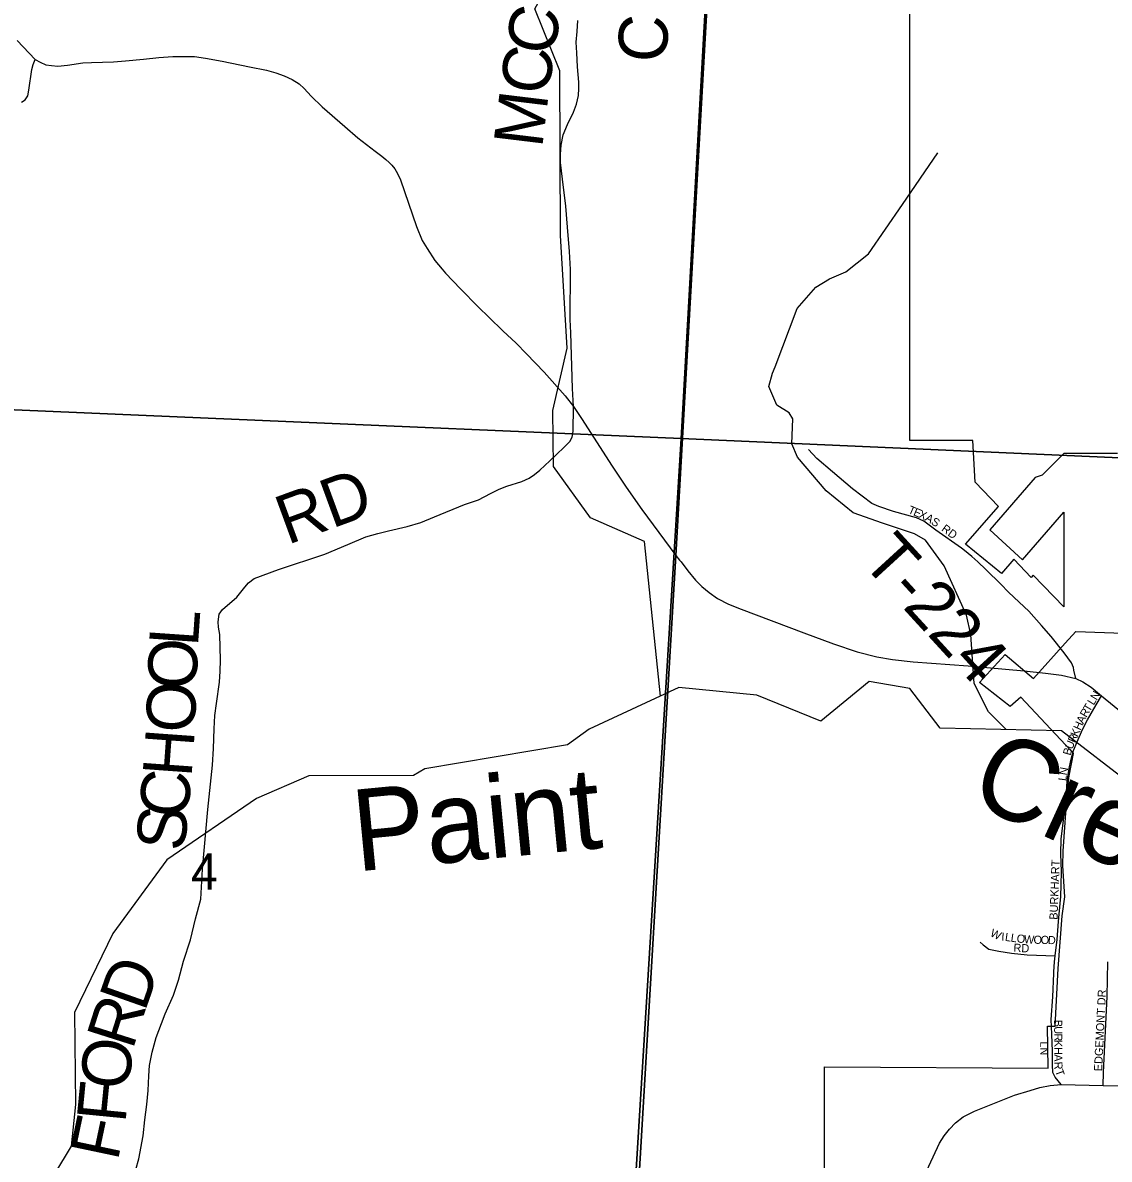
# Model space of a CAD drawing. Extents: x 1878108 to 2183446, y 146837 to 508383.
# Drawn here: x 2042273 to 2048929, y 293449 to 300413 of the extents above; entities that cross this region are included whole.
import ezdxf

# ---------------------------------------------------------------- set-up
doc = ezdxf.new("R2010")
doc.units = 0
for name, color, linetype in [('GM_X_City_Street', 7, 'Continuous'), ('GM_X_City_Street_Text', 7, 'Continuous'), ('GM_X_Corporation', 7, 'Continuous'), ('GM_X_County_Road', 7, 'Continuous'), ('GM_X_County_Road_Text', 7, 'Continuous'), ('GM_X_Minor_River', 7, 'Continuous'), ('GM_X_Minor_River_Text', 7, 'Continuous'), ('GM_X_Section', 7, 'Continuous'), ('GM_X_Section_Text', 7, 'Continuous'), ('GM_X_State_Route', 7, 'Continuous'), ('GM_X_Township', 7, 'Continuous'), ('GM_X_Township_Road', 7, 'Continuous'), ('GM_X_Township_Road_Text', 7, 'Continuous'), ('GM_X_Township_Subdivision', 7, 'Continuous'), ('GM_X_Township_Subdivision_Text', 7, 'Continuous')]:
    doc.layers.add(name, color=color, linetype=linetype)

msp = doc.modelspace()

# ---------------------------------------------------------------- linework, layer by layer
at = {"layer": 'GM_X_City_Street'}
for points in [[(2048723.1, 296394.8), (2048712.2, 296446.1)], [(2048696.9, 295908.5), (2048709.8, 295953.8), (2048732, 296006.9), (2048765.2, 296081.2), (2048794.3, 296141.8), (2048848.3, 296234.1), (2048882, 296288.6)], [(2048891.1, 293900), (2048893.7, 293980), (2048914.9, 294445.8), (2048914.8, 294445.9), (2048920.8, 294657.6)], [(2048633.8, 293906.7), (2048596.7, 293951.4), (2048583.9, 293980), (2048580.1, 294026.5), (2048580.1, 294111.6), (2048577.6, 294212.6)]]:
    msp.add_lwpolyline(points, dxfattribs=at)
at = {"layer": 'GM_X_Corporation'}
for points in [[(2048978.2, 297773.1), (2048650.2, 297773.1), (2048517.9, 297640.9), (2048475.7, 297625.5), (2048197.5, 297305.5), (2048396.9, 297122), (2048650.1, 297413.2), (2048650.1, 296834.3), (2048462.6, 297028.5), (2048450.1, 297014.2), (2048343.1, 297124.9), (2048267.7, 297038.2), (2048048.2, 297216.9), (2048250.3, 297449.3), (2048107.2, 297597.5), (2048093.8, 297853.1), (2047707.8, 297853.1), (2047707.7, 300742.9)], [(2047182.7, 292397.4), (2047183.4, 294014.9), (2048554.9, 294007.4), (2048550.8, 294264.7), (2048571.8, 294264.2), (2048596.2, 294263.4), (2048615.2, 294618.2), (2048639.2, 294940.7), (2048655.9, 295056.6), (2048643.8, 295246.6), (2048645.9, 295335.9), (2048673.7, 295716.7), (2048683.2, 295797.2), (2048709.9, 295935), (2048690.5, 295955.4), (2048386.1, 296281), (2048321.8, 296222.8), (2048133, 296369.3), (2048291.7, 296541.8), (2048464.4, 296395.3), (2048657.6, 296611.1), (2048723.5, 296682.3), (2049892.6, 296642.2)]]:
    msp.add_lwpolyline(points, dxfattribs=at)
at = {"layer": 'GM_X_County_Road'}
msp.add_lwpolyline([(2045647.3, 298061.2), (2045640.7, 298170.9), (2045629.6, 298513.3), (2045625.3, 298594.2), (2045629, 298900.7), (2045621.5, 299010), (2045610.2, 299159.5), (2045598.9, 299288.9), (2045578.8, 299453.4), (2045567.5, 299556.4), (2045566.2, 299605.4), (2045571.2, 299661.9), (2045582.5, 299726), (2045608.9, 299788.8), (2045646.6, 299864.2), (2045665.4, 299914.4), (2045678, 299967.2), (2045679.3, 300009.9), (2045679.3, 300047.6), (2045671.7, 300143), (2045666.7, 300228.4), (2045662.9, 300293.8), (2045668.5, 300359.5), (2045673, 300425.7)], dxfattribs=at)
at = {"layer": 'GM_X_Minor_River'}
for points in [[(2046178.6, 296286.3), (2046081, 297234.6), (2045750.4, 297379.9), (2045523.8, 297694.5), (2045519.3, 298037.1), (2045608.4, 298418.6), (2045567.3, 299109.5), (2045562, 300117.5), (2045408.7, 300498.8), (2045575.1, 300796.9), (2045599.4, 301083.7)], [(2048296.3, 296081.2), (2048189.8, 296189.9), (2048101.8, 296364.4), (2048079.9, 296663.5), (2048053.9, 296781.9), (2047917.9, 297084.8), (2047801.9, 297241.2), (2047735.8, 297281.3), (2047539.7, 297345.3), (2047359.6, 297409.4), (2047193.5, 297543.7), (2047019.5, 297750.2), (2046983.5, 297832.5), (2046989.5, 297985), (2046967.5, 298023.1), (2046891.5, 298069.2), (2046843.5, 298183.6), (2046865.5, 298265.9), (2046881.6, 298304.1), (2047015.8, 298661.5), (2047131.9, 298792.1), (2047214, 298844.4), (2047314.1, 298886.6), (2047454.2, 298997.2), (2047662.5, 299298.5), (2047878.8, 299615.9)], [(2049071.3, 295738.5), (2048635.9, 296073.3), (2047892.1, 296090.6), (2047706.5, 296333.5), (2047457.4, 296375.3), (2047161.9, 296132.2), (2046768.9, 296293), (2046291.3, 296338.8), (2045743.4, 296083.5), (2045610.4, 295988.1), (2044736.4, 295840), (2044666.8, 295799.3), (2044025.4, 295797.6), (2043704.5, 295658.5), (2043156.3, 295282.9), (2042825.5, 294831.1), (2042589.3, 294348.1), (2042596.7, 293785.2), (2042570, 293528.5), (2042275.8, 293040.9), (2042389.6, 292771.4), (2043259.2, 292031.8)]]:
    msp.add_lwpolyline(points, dxfattribs=at)
at = {"layer": 'GM_X_Section'}
for points in [[(2046608.5, 303278.4), (2046305.3, 297866), (2040795.1, 298102.8), (2041118.3, 303517.3)], [(2046608.5, 303278.4), (2052098.8, 303033.5), (2051725.6, 297626.8), (2046305.3, 297866)], [(2046305.3, 297866), (2045974, 292455.4), (2040477.8, 292684.4), (2040533.2, 293648.8), (2040666, 295882.7), (2040795.1, 298102.8)], [(2046305.3, 297866), (2051725.6, 297626.8), (2051406.4, 292766.4), (2051368.5, 292736.3), (2051314.6, 292690.1), (2051262.8, 292641.9), (2051200.9, 292591.7), (2051101.2, 292499.3), (2050981.6, 292386.8), (2050889.9, 292300.5), (2050854, 292266.4), (2050820.1, 292230.3), (2045974, 292455.4)]]:
    msp.add_lwpolyline(points, close=True, dxfattribs=at)
at = {"layer": 'GM_X_State_Route'}
for points in [[(2042238.6, 300303.5), (2042348, 300186.7), (2042379, 300171.9), (2042414.7, 300155.2), (2042449.2, 300149.7), (2042487.1, 300147.4), (2042547.3, 300153), (2042639.8, 300166.4), (2042694.4, 300169.7), (2042829.3, 300173.1), (2042902.9, 300179.7), (2043013.2, 300189.8), (2043105.7, 300198.7), (2043192.6, 300206.5), (2043251.7, 300206.5), (2043325.3, 300206.5), (2043392.2, 300196.5), (2043493.6, 300176.4), (2043661.9, 300143), (2043766.7, 300122.9), (2043823.5, 300106.2), (2043873.7, 300087.2), (2043922.7, 300063.8), (2043966.2, 300038.2), (2043997.4, 300009.2), (2044039.7, 299962.4), (2044106.7, 299897.9), (2044244.9, 299776), (2044326.2, 299708.3), (2044432.1, 299625.8), (2044472.2, 299594.6), (2044497.8, 299574.5), (2044517.9, 299555.6), (2044534.6, 299540), (2044551.6, 299517.6), (2044569.2, 299488.7), (2044585.9, 299450.8), (2044684, 299163.2), (2044718.5, 299077.4), (2044749.7, 299028.4), (2044797.7, 298955.9), (2044842.8, 298903.2)], [(2044842.8, 298903.2), (2044863.4, 298879), (2044953.7, 298782.1), (2045061.8, 298671.7), (2045129.8, 298606), (2045213.4, 298525.7), (2045294.8, 298449.9), (2045359.2, 298383.6), (2045466.7, 298270.6), (2045596.3, 298126.6), (2045647.3, 298061.2), (2045700.5, 297981.4), (2045878.9, 297702.2), (2045969.7, 297567), (2046065, 297430.7), (2046274.1, 297148.3), (2046296.7, 297119.9)], [(2046296.7, 297119.9), (2046305.8, 297108.5), (2046346.5, 297055.1), (2046394.1, 296996.9), (2046432.9, 296957.6), (2046477.2, 296921.1), (2046529.3, 296885.6), (2046596.9, 296850.1), (2046673.3, 296820.2), (2047057.8, 296675.1), (2047238.4, 296606.4), (2047384.7, 296557.6), (2047504.3, 296526.6), (2047600.7, 296511.1), (2047728.1, 296496.7), (2048063.9, 296472.3), (2048406.3, 296441.3), (2048537, 296428), (2048635.6, 296415.8), (2048723.1, 296394.8)], [(2048723.1, 296394.8), (2048766.4, 296374.8), (2048817.3, 296340.5), (2048882, 296288.6), (2049036.7, 296162.1)], [(2047199.6, 292441), (2047285.6, 292522.8), (2047355.2, 292596.4), (2047387.5, 292633.8), (2047434, 292697.1), (2047546.1, 292877.6), (2047627.6, 293014.6), (2047702.4, 293154), (2047823.8, 293405.7), (2047888.3, 293546.3), (2047916.7, 293592.8), (2047948.9, 293634.1), (2047986.4, 293671.5), (2048034.1, 293707.7), (2048103.8, 293742.5), (2048347.8, 293840.6), (2048443.3, 293870.3), (2048503.9, 293888.4), (2048567.2, 293900), (2048633.8, 293906.7)], [(2048633.8, 293906.7), (2048891.1, 293900), (2049025.8, 293897.7), (2049162.3, 293890.2), (2049224.6, 293879.9), (2049272.2, 293862), (2049313.9, 293836.5), (2049444.1, 293756.7), (2049556.9, 293682.6)]]:
    msp.add_lwpolyline(points, dxfattribs=at)
at = {"layer": 'GM_X_Township'}
for points in [[(2041416.6, 309015.4), (2043687.2, 308920.5), (2044671.3, 308870.3), (2046896.4, 308713), (2046850.7, 307315.9), (2046837.6, 306990.7), (2046818.9, 306761.3), (2046274.1, 297148.3), (2046004.2, 292592), (2045984.8, 292287.1), (2045909.9, 291035.1), (2045645.1, 286985.8), (2045292.2, 281208.8), (2045231.9, 280221.7), (2044993.2, 276329), (2043134.5, 276417.7), (2042678.2, 276439.4), (2039443.8, 276593.8)], [(2045292.2, 281208.8), (2045645.1, 286985.8), (2045909.9, 291035.1), (2045984.8, 292287.1), (2046004.2, 292592), (2046274.1, 297148.3), (2046818.9, 306761.3), (2046837.6, 306990.7), (2046850.7, 307315.9), (2046896.4, 308713), (2049918.6, 308616.7), (2052395.6, 308421.9), (2058453.5, 308204.9)]]:
    msp.add_lwpolyline(points, dxfattribs=at)
at = {"layer": 'GM_X_Township_Road'}
for points in [[(2044447.8, 297282.2), (2044513.8, 297300), (2044626.8, 297325.5), (2044711, 297351), (2044794.1, 297385.3), (2044978.1, 297460.7), (2045064.5, 297489.5), (2045138.7, 297527.1), (2045191.9, 297553.7), (2045238.4, 297572.6), (2045330.4, 297602.5), (2045374.7, 297622.4), (2045406.9, 297643.5), (2045440.1, 297671.2), (2045502.1, 297728.8), (2045586.4, 297810.8), (2045624, 297847.4), (2045638.4, 297873.9), (2045644, 297907.2), (2045647.3, 298061.2)], [(2042964.9, 293385.7), (2042983.6, 293450.8), (2043010.2, 293592.6), (2043021.3, 293690.1), (2043032.4, 293784.3), (2043041.3, 293870.7), (2043045.7, 293960.4), (2043050.1, 294022.5), (2043065.6, 294104.5), (2043090, 294195.3), (2043123.2, 294280.7), (2043145.4, 294340.5), (2043195.3, 294454.6), (2043226.3, 294546.6), (2043258.4, 294661.8), (2043300.5, 294793.7), (2043330.4, 294921.9), (2043363.7, 295041.9), (2043373.7, 295225.8), (2043406.9, 295592.5), (2043434.6, 295864), (2043441.2, 295964.8), (2043445.7, 296086.7), (2043450.1, 296168.7), (2043459, 296241.8), (2043478.9, 296371.5), (2043482.2, 296439.1), (2043483.4, 296506.7), (2043480, 296665.1), (2043472.3, 296709.4), (2043470.1, 296742.7), (2043476.7, 296788.1), (2043495.5, 296818), (2043584.2, 296893.4), (2043634, 296954.3), (2043656.2, 296980.9), (2043689.4, 297006.4), (2043840.1, 297062.9), (2044122.7, 297157.1), (2044263.4, 297214.7), (2044374.2, 297262.3), (2044447.8, 297282.2)], [(2048122.5, 297109.6), (2048087.1, 297142.7), (2048042.6, 297177.8)], [(2048310.3, 296926), (2048266.6, 296970.9), (2048172.5, 297062.9), (2048122.5, 297109.6)], [(2048712.2, 296446.1), (2048708.7, 296462.3), (2048696.5, 296491.1), (2048652.2, 296551), (2048572.5, 296651.8), (2048512.6, 296719.4), (2048435.1, 296806.9), (2048345.3, 296890), (2048310.3, 296926)]]:
    msp.add_lwpolyline(points, dxfattribs=at)
at = {"layer": 'GM_X_Township_Subdivision'}
for points in [[(2042264, 299926), (2042287.8, 299940.7), (2042303.7, 299964.5), (2042310.5, 299999.7), (2042327.5, 300125.5), (2042335.5, 300156.1), (2042348, 300186.7)], [(2048042.6, 297177.8), (2048024, 297192.5), (2047866.6, 297304.4), (2047792.4, 297358.7), (2047748.1, 297378.7), (2047607.4, 297417.4), (2047516.5, 297447.4), (2047473.3, 297466.2), (2047355.9, 297557.1), (2047232.9, 297660.1), (2047136.5, 297743.2), (2047086.6, 297797.5)], [(2048677.6, 295804.3), (2048683.3, 295842.4), (2048692.4, 295892.7), (2048696.9, 295908.5)], [(2048665.8, 295699), (2048671.7, 295765), (2048677.6, 295804.3)], [(2048618.6, 294906), (2048622.7, 294950.6), (2048631.3, 295058.7), (2048634.3, 295131.2), (2048635.6, 295211.3), (2048631.7, 295319.7), (2048634.3, 295411.3), (2048648.5, 295523.6), (2048658.8, 295621.7), (2048665.8, 295699)], [(2048589, 294587.9), (2048589.4, 294597.3), (2048592.6, 294657.4), (2048596.9, 294695), (2048608.5, 294795.7), (2048618.6, 294906)], [(2048138.7, 294778.9), (2048156.7, 294762.1), (2048191.6, 294736.3), (2048252.2, 294723.4), (2048329.7, 294710.5), (2048426.5, 294701.5), (2048596.9, 294695)], [(2048577.6, 294212.6), (2048577.5, 294216.2), (2048572.3, 294305.2), (2048582.7, 294444.6), (2048589, 294587.9)]]:
    msp.add_lwpolyline(points, dxfattribs=at)

# ---------------------------------------------------------------- texts
at = {"layer": 'GM_X_City_Street_Text'}
for s, rotation, p in [('N', 58.81687, (2048851.4, 296257.4)), ('L', 58.81133, (2048833.1, 296227.3)), ('R', 59.76104, (2048788.2, 296151.9)), ('T', 58.81133, (2048808.1, 296185.9)), ('H', 66.10407, (2048752, 296073.3)), ('A', 64.37317, (2048769.7, 296113.2)), ('R', 66.09668, (2048718.2, 295996.8)), ('K', 66.10407, (2048734.2, 296033.1)), ('U', 67.55328, (2048701.5, 295956.5)), ('B', 74.0079, (2048691.1, 295919.8)), ('EDGEMONT DR', 87.16522, (2048884.5, 293986.9)), ('U', 270.06559, (2048591, 294263.6)), ('B', 270.07288, (2048591, 294303.2)), ('LN', 270, (2048505.9, 294171.2)), ('R', 270.06529, (2048591.1, 294219.6)), ('K', 270.06037, (2048591.1, 294180)), ('H', 270.08288, (2048591.2, 294136)), ('A', 270.06559, (2048591.2, 294092)), ('R', 272.4399, (2048591.3, 294045.7)), ('T', 289.52054, (2048596.1, 293990.2))]:
    msp.add_text(s, height=50, rotation=rotation, dxfattribs=at).set_placement(p)
at = {"layer": 'GM_X_County_Road_Text'}
for s, rotation, p in [('C', 80.55115, (2045525.2, 300204.8)), ('C', 86.42846, (2046214.2, 300163.4)), ('C', 82.46106, (2045493.3, 299963.1)), ('M', 83.09258, (2045454.2, 299640.7))]:
    msp.add_text(s, height=300, rotation=rotation, dxfattribs=at).set_placement(p)
at = {"layer": 'GM_X_Minor_River_Text'}
for s, rotation, p in [('Creek', 335.51619, (2048051, 295646.3)), ('Paint', 5.51139, (2044317.1, 295211.4))]:
    msp.add_text(s, height=499.99, rotation=rotation, dxfattribs=at).set_placement(p)
at = {"layer": 'GM_X_Section_Text'}
msp.add_text('4', height=221, rotation=0.00001, dxfattribs=at).set_placement((2043303.7, 295101.5))
at = {"layer": 'GM_X_Township_Road_Text'}
for s, rotation, p in [('RD', 20.14305, (2043894, 297212.1)), ('T-224', 312.46257, (2047402.3, 297110.6)), ('L', 86.05421, (2043345.4, 296585.8)), ('O', 88.02022, (2043336.5, 296324.7)), ('O', 87.68812, (2043325.8, 296059)), ('H', 85.87505, (2043306.2, 295785.4)), ('C', 84.62309, (2043282.5, 295532.9)), ('S', 84.55605, (2043263.3, 295331.1)), ('D', 70.5743, (2043019.5, 294346.3)), ('R', 72.35004, (2042945.6, 294113.8)), ('O', 83.91967, (2042920.9, 293866.9)), ('F', 84.42024, (2042901.3, 293666.2)), ('F', 78.1009, (2042854.1, 293432.4))]:
    msp.add_text(s, height=300, rotation=rotation, dxfattribs=at).set_placement(p)
at = {"layer": 'GM_X_Township_Subdivision_Text'}
for s, rotation, p in [('T', 337.24984, (2047691.9, 297409.5)), ('E', 337.24984, (2047724.4, 297395.9)), ('X', 336.10408, (2047756.6, 297382.4)), ('A', 329.81594, (2047795.6, 297365.2)), ('S', 328.03807, (2047833.2, 297343.3)), ('RD', 323.74111, (2047896.3, 297302.7)), ('N', 80.00594, (2048668.9, 295799.1)), ('L', 82.76651, (2048664.6, 295764.8)), ('BURKHART', 87.87459, (2048611.7, 294915.7)), ('W', 335.00647, (2048194.8, 294817.6)), ('I', 356.77321, (2048266.6, 294788.4)), ('L', 352.24468, (2048287.6, 294787.3)), ('L', 352.26802, (2048322.5, 294782.5)), ('O', 354.96973, (2048359.9, 294777.5)), ('W', 355.85395, (2048404.6, 294773.6)), ('O', 358.64165, (2048464.3, 294769.3)), ('O', 358.55753, (2048508.2, 294768.3)), ('D', 358.56278, (2048552.2, 294767.2)), ('RD', 357.13923, (2048340.8, 294720.4))]:
    msp.add_text(s, height=50, rotation=rotation, dxfattribs=at).set_placement(p)

doc.saveas('drawing.dxf')
